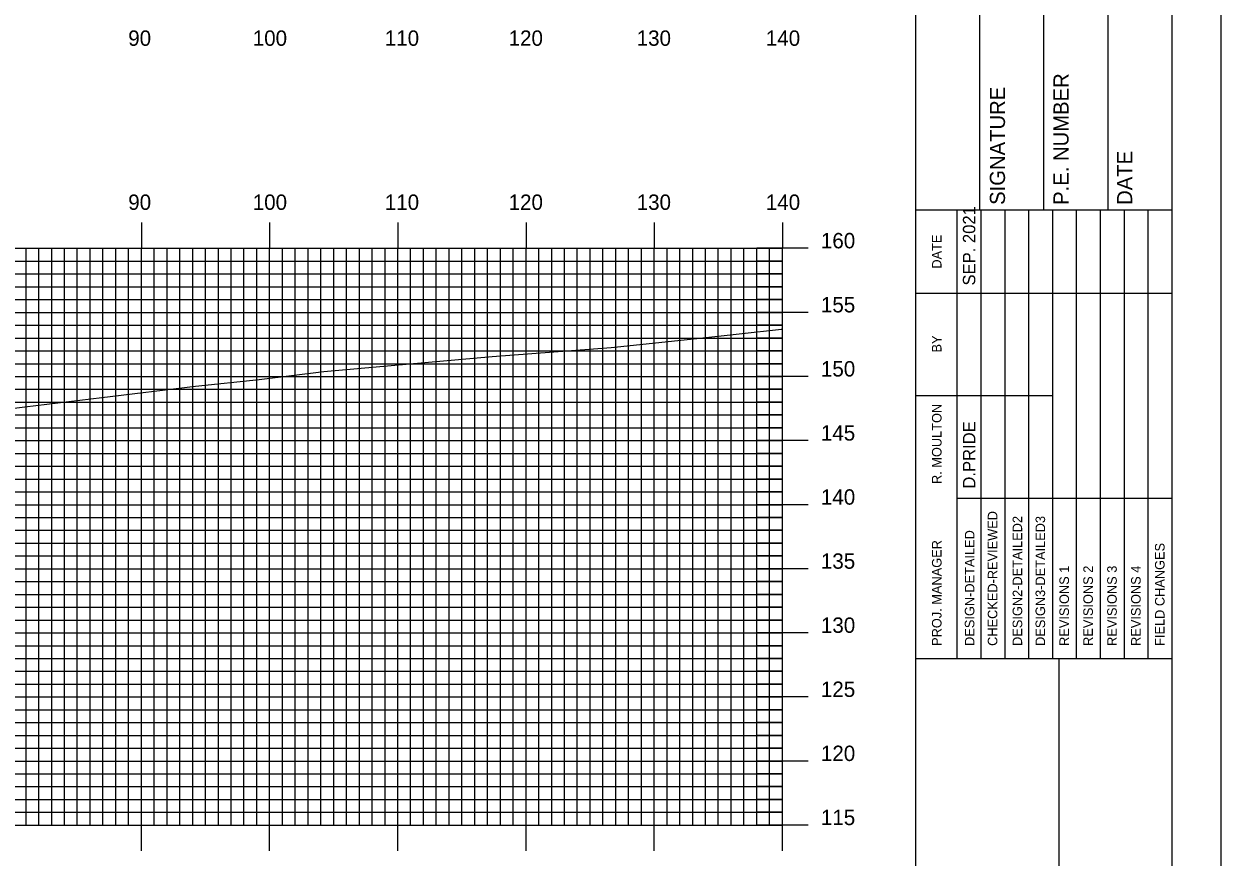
# Model space of a CAD drawing. Extents: x 1782647 to 1782990, y 442591 to 442811.
# Drawn here: x 1782893.8 to 1782987.2, y 442671.2 to 442736.2 of the extents above; entities that cross this region are included whole.
import ezdxf

# ---------------------------------------------------------------- set-up
doc = ezdxf.new("R2010")
doc.units = 0
for name, color, linetype in [('BORDER', 7, 'Continuous'), ('H_V ANNOTATION', 7, 'Continuous'), ('MAJOR', 7, 'Continuous'), ('MINOR', 7, 'Continuous'), ('PLOT BOUNDARY', 7, 'Continuous'), ('S_Roadway_Centerline', 7, 'Continuous')]:
    doc.layers.add(name, color=color, linetype=linetype)

msp = doc.modelspace()

# ---------------------------------------------------------------- linework, layer by layer
at = {"layer": 'BORDER'}
for p, q in [((1782963.347, 442596.665), (1782963.347, 442806.665)), ((1782968.347, 442721.671), (1782968.347, 442738.966)), ((1782968.347, 442721.671), (1782968.347, 442738.966)), ((1782973.347, 442721.671), (1782973.347, 442738.966)), ((1782973.347, 442721.671), (1782973.347, 442738.966)), ((1782978.347, 442721.671), (1782978.347, 442738.966)), ((1782978.347, 442721.671), (1782978.347, 442738.966)), ((1782963.347, 442721.671), (1782983.347, 442721.671)), ((1782963.347, 442721.671), (1782983.347, 442721.671)), ((1782963.347, 442686.671), (1782983.347, 442686.671)), ((1782963.347, 442686.671), (1782983.347, 442686.671)), ((1782974.529, 442616.671), (1782974.529, 442686.671)), ((1782974.529, 442616.671), (1782974.529, 442686.671))]:
    msp.add_line(p, q, dxfattribs=at)
msp.add_lwpolyline([(1782663.347, 442596.665), (1782983.347, 442596.665), (1782983.347, 442806.665), (1782663.347, 442806.665)], close=True, dxfattribs=at)
for points in [[(1782966.577, 442715.171), (1782966.577, 442721.671)], [(1782966.577, 442715.171), (1782966.577, 442721.671)], [(1782968.442, 442686.677), (1782968.442, 442721.671)], [(1782968.442, 442686.677), (1782968.442, 442721.671)], [(1782970.305, 442721.671), (1782970.305, 442686.677)], [(1782970.305, 442721.671), (1782970.305, 442686.677)], [(1782972.169, 442686.677), (1782972.169, 442721.671)], [(1782972.169, 442686.677), (1782972.169, 442721.671)], [(1782974.032, 442686.677), (1782974.032, 442721.671)], [(1782974.032, 442686.677), (1782974.032, 442721.671)], [(1782975.895, 442686.677), (1782975.895, 442721.671)], [(1782975.895, 442686.677), (1782975.895, 442721.671)], [(1782977.759, 442686.677), (1782977.759, 442721.671)], [(1782977.759, 442686.677), (1782977.759, 442721.671)], [(1782979.622, 442686.677), (1782979.622, 442721.671)], [(1782979.622, 442686.677), (1782979.622, 442721.671)], [(1782981.485, 442686.677), (1782981.485, 442721.671)], [(1782981.485, 442686.677), (1782981.485, 442721.671)], [(1782966.579, 442686.677), (1782966.579, 442720.259)], [(1782966.579, 442686.677), (1782966.579, 442720.259)], [(1782963.347, 442715.171), (1782983.347, 442715.171)], [(1782963.347, 442715.171), (1782983.347, 442715.171)], [(1782963.347, 442707.171), (1782966.579, 442707.171)], [(1782963.347, 442707.171), (1782966.579, 442707.171)], [(1782966.577, 442707.171), (1782974.03, 442707.171)], [(1782966.577, 442707.171), (1782974.03, 442707.171)], [(1782966.577, 442699.171), (1782983.347, 442699.171)], [(1782966.577, 442699.171), (1782983.347, 442699.171)]]:
    msp.add_lwpolyline(points, dxfattribs=at)
at = {"layer": 'MAJOR'}
for p, q in [((1782902.947, 442720.669), (1782902.947, 442718.665)), ((1782912.947, 442720.669), (1782912.947, 442718.665)), ((1782922.947, 442720.669), (1782922.947, 442718.665)), ((1782932.947, 442720.669), (1782932.947, 442718.665)), ((1782942.947, 442720.669), (1782942.947, 442718.665)), ((1782952.947, 442720.669), (1782952.947, 442718.665)), ((1782672.947, 442718.665), (1782952.947, 442718.665)), ((1782672.947, 442718.665), (1782952.947, 442718.665)), ((1782902.947, 442673.665), (1782902.947, 442718.665)), ((1782912.947, 442673.665), (1782912.947, 442718.665)), ((1782922.947, 442673.665), (1782922.947, 442718.665)), ((1782932.947, 442673.665), (1782932.947, 442718.665)), ((1782942.947, 442673.665), (1782942.947, 442718.665)), ((1782954.951, 442718.665), (1782950.943, 442718.665)), ((1782952.947, 442673.665), (1782952.947, 442718.665)), ((1782952.947, 442673.665), (1782952.947, 442718.665)), ((1782672.947, 442713.665), (1782952.947, 442713.665)), ((1782954.951, 442713.665), (1782950.943, 442713.665)), ((1782672.947, 442708.665), (1782952.947, 442708.665)), ((1782954.951, 442708.665), (1782950.943, 442708.665)), ((1782672.947, 442703.665), (1782952.947, 442703.665)), ((1782954.951, 442703.665), (1782950.943, 442703.665)), ((1782672.947, 442698.665), (1782952.947, 442698.665)), ((1782954.951, 442698.665), (1782950.943, 442698.665)), ((1782672.947, 442693.665), (1782952.947, 442693.665)), ((1782954.951, 442693.665), (1782950.943, 442693.665)), ((1782672.947, 442688.665), (1782952.947, 442688.665)), ((1782954.951, 442688.665), (1782950.943, 442688.665)), ((1782672.947, 442683.665), (1782952.947, 442683.665)), ((1782954.951, 442683.665), (1782950.943, 442683.665)), ((1782672.947, 442678.665), (1782952.947, 442678.665)), ((1782954.951, 442678.665), (1782950.943, 442678.665)), ((1782672.947, 442673.665), (1782952.947, 442673.665)), ((1782672.947, 442673.665), (1782952.947, 442673.665)), ((1782902.947, 442671.661), (1782902.947, 442673.665)), ((1782912.947, 442671.661), (1782912.947, 442673.665)), ((1782922.947, 442671.661), (1782922.947, 442673.665)), ((1782932.947, 442671.661), (1782932.947, 442673.665)), ((1782942.947, 442671.661), (1782942.947, 442673.665)), ((1782954.951, 442673.665), (1782950.943, 442673.665)), ((1782952.947, 442671.661), (1782952.947, 442673.665))]:
    msp.add_line(p, q, dxfattribs=at)
at = {"layer": 'MINOR'}
for p, q in [((1782893.947, 442673.665), (1782893.947, 442718.665)), ((1782894.947, 442673.665), (1782894.947, 442718.665)), ((1782895.947, 442673.665), (1782895.947, 442718.665)), ((1782896.947, 442673.665), (1782896.947, 442718.665)), ((1782897.947, 442673.665), (1782897.947, 442718.665)), ((1782898.947, 442673.665), (1782898.947, 442718.665)), ((1782899.947, 442673.665), (1782899.947, 442718.665)), ((1782900.947, 442673.665), (1782900.947, 442718.665)), ((1782901.947, 442673.665), (1782901.947, 442718.665)), ((1782903.947, 442673.665), (1782903.947, 442718.665)), ((1782904.947, 442673.665), (1782904.947, 442718.665)), ((1782905.947, 442673.665), (1782905.947, 442718.665)), ((1782906.947, 442673.665), (1782906.947, 442718.665)), ((1782907.947, 442673.665), (1782907.947, 442718.665)), ((1782908.947, 442673.665), (1782908.947, 442718.665)), ((1782909.947, 442673.665), (1782909.947, 442718.665)), ((1782910.947, 442673.665), (1782910.947, 442718.665)), ((1782911.947, 442673.665), (1782911.947, 442718.665)), ((1782913.947, 442673.665), (1782913.947, 442718.665)), ((1782914.947, 442673.665), (1782914.947, 442718.665)), ((1782915.947, 442673.665), (1782915.947, 442718.665)), ((1782916.947, 442673.665), (1782916.947, 442718.665)), ((1782917.947, 442673.665), (1782917.947, 442718.665)), ((1782918.947, 442673.665), (1782918.947, 442718.665)), ((1782919.947, 442673.665), (1782919.947, 442718.665)), ((1782920.947, 442673.665), (1782920.947, 442718.665)), ((1782921.947, 442673.665), (1782921.947, 442718.665)), ((1782923.947, 442673.665), (1782923.947, 442718.665)), ((1782924.947, 442673.665), (1782924.947, 442718.665)), ((1782925.947, 442673.665), (1782925.947, 442718.665)), ((1782926.947, 442673.665), (1782926.947, 442718.665)), ((1782927.947, 442673.665), (1782927.947, 442718.665)), ((1782928.947, 442673.665), (1782928.947, 442718.665)), ((1782929.947, 442673.665), (1782929.947, 442718.665)), ((1782930.947, 442673.665), (1782930.947, 442718.665)), ((1782931.947, 442673.665), (1782931.947, 442718.665)), ((1782933.947, 442673.665), (1782933.947, 442718.665)), ((1782934.947, 442673.665), (1782934.947, 442718.665)), ((1782935.947, 442673.665), (1782935.947, 442718.665)), ((1782936.947, 442673.665), (1782936.947, 442718.665)), ((1782937.947, 442673.665), (1782937.947, 442718.665)), ((1782938.947, 442673.665), (1782938.947, 442718.665)), ((1782939.947, 442673.665), (1782939.947, 442718.665)), ((1782940.947, 442673.665), (1782940.947, 442718.665)), ((1782941.947, 442673.665), (1782941.947, 442718.665)), ((1782943.947, 442673.665), (1782943.947, 442718.665)), ((1782944.947, 442673.665), (1782944.947, 442718.665)), ((1782945.947, 442673.665), (1782945.947, 442718.665)), ((1782946.947, 442673.665), (1782946.947, 442718.665)), ((1782947.947, 442673.665), (1782947.947, 442718.665)), ((1782948.947, 442673.665), (1782948.947, 442718.665)), ((1782949.947, 442673.665), (1782949.947, 442718.665)), ((1782950.947, 442673.665), (1782950.947, 442718.665)), ((1782951.947, 442673.665), (1782951.947, 442718.665)), ((1782672.947, 442717.665), (1782952.947, 442717.665)), ((1782952.947, 442717.665), (1782950.943, 442717.665)), ((1782672.947, 442716.665), (1782952.947, 442716.665)), ((1782952.947, 442716.665), (1782950.943, 442716.665)), ((1782672.947, 442715.665), (1782952.947, 442715.665)), ((1782952.947, 442715.665), (1782950.943, 442715.665)), ((1782672.947, 442714.665), (1782952.947, 442714.665)), ((1782952.947, 442714.665), (1782950.943, 442714.665)), ((1782672.947, 442712.665), (1782952.947, 442712.665)), ((1782952.947, 442712.665), (1782950.943, 442712.665)), ((1782672.947, 442711.665), (1782952.947, 442711.665)), ((1782952.947, 442711.665), (1782950.943, 442711.665)), ((1782672.947, 442710.665), (1782952.947, 442710.665)), ((1782952.947, 442710.665), (1782950.943, 442710.665)), ((1782672.947, 442709.665), (1782952.947, 442709.665)), ((1782952.947, 442709.665), (1782950.943, 442709.665)), ((1782672.947, 442707.665), (1782952.947, 442707.665)), ((1782952.947, 442707.665), (1782950.943, 442707.665)), ((1782672.947, 442706.665), (1782952.947, 442706.665)), ((1782952.947, 442706.665), (1782950.943, 442706.665)), ((1782672.947, 442705.665), (1782952.947, 442705.665)), ((1782952.947, 442705.665), (1782950.943, 442705.665)), ((1782672.947, 442704.665), (1782952.947, 442704.665)), ((1782952.947, 442704.665), (1782950.943, 442704.665)), ((1782672.947, 442702.665), (1782952.947, 442702.665)), ((1782952.947, 442702.665), (1782950.943, 442702.665)), ((1782672.947, 442701.665), (1782952.947, 442701.665)), ((1782952.947, 442701.665), (1782950.943, 442701.665)), ((1782672.947, 442700.665), (1782952.947, 442700.665)), ((1782952.947, 442700.665), (1782950.943, 442700.665)), ((1782672.947, 442699.665), (1782952.947, 442699.665)), ((1782952.947, 442699.665), (1782950.943, 442699.665)), ((1782672.947, 442697.665), (1782952.947, 442697.665)), ((1782952.947, 442697.665), (1782950.943, 442697.665)), ((1782672.947, 442696.665), (1782952.947, 442696.665)), ((1782952.947, 442696.665), (1782950.943, 442696.665)), ((1782672.947, 442695.665), (1782952.947, 442695.665)), ((1782952.947, 442695.665), (1782950.943, 442695.665)), ((1782672.947, 442694.665), (1782952.947, 442694.665)), ((1782952.947, 442694.665), (1782950.943, 442694.665)), ((1782672.947, 442692.665), (1782952.947, 442692.665)), ((1782952.947, 442692.665), (1782950.943, 442692.665)), ((1782672.947, 442691.665), (1782952.947, 442691.665)), ((1782952.947, 442691.665), (1782950.943, 442691.665)), ((1782672.947, 442690.665), (1782952.947, 442690.665)), ((1782952.947, 442690.665), (1782950.943, 442690.665)), ((1782672.947, 442689.665), (1782952.947, 442689.665)), ((1782952.947, 442689.665), (1782950.943, 442689.665)), ((1782672.947, 442687.665), (1782952.947, 442687.665)), ((1782952.947, 442687.665), (1782950.943, 442687.665)), ((1782672.947, 442686.665), (1782952.947, 442686.665)), ((1782952.947, 442686.665), (1782950.943, 442686.665)), ((1782672.947, 442685.665), (1782952.947, 442685.665)), ((1782952.947, 442685.665), (1782950.943, 442685.665)), ((1782672.947, 442684.665), (1782952.947, 442684.665)), ((1782952.947, 442684.665), (1782950.943, 442684.665)), ((1782672.947, 442682.665), (1782952.947, 442682.665)), ((1782952.947, 442682.665), (1782950.943, 442682.665)), ((1782672.947, 442681.665), (1782952.947, 442681.665)), ((1782952.947, 442681.665), (1782950.943, 442681.665)), ((1782672.947, 442680.665), (1782952.947, 442680.665)), ((1782952.947, 442680.665), (1782950.943, 442680.665)), ((1782672.947, 442679.665), (1782952.947, 442679.665)), ((1782952.947, 442679.665), (1782950.943, 442679.665)), ((1782672.947, 442677.665), (1782952.947, 442677.665)), ((1782952.947, 442677.665), (1782950.943, 442677.665)), ((1782672.947, 442676.665), (1782952.947, 442676.665)), ((1782952.947, 442676.665), (1782950.943, 442676.665)), ((1782672.947, 442675.665), (1782952.947, 442675.665)), ((1782952.947, 442675.665), (1782950.943, 442675.665)), ((1782672.947, 442674.665), (1782952.947, 442674.665)), ((1782952.947, 442674.665), (1782950.943, 442674.665))]:
    msp.add_line(p, q, dxfattribs=at)
at = {"layer": 'PLOT BOUNDARY'}
msp.add_lwpolyline([(1782647.16, 442590.547), (1782987.16, 442590.547), (1782987.16, 442810.547), (1782647.16, 442810.547)], close=True, dxfattribs=at)
at = {"layer": 'S_Roadway_Centerline'}
msp.add_lwpolyline([(1782884.098, 442705.086), (1782893.859, 442706.3), (1782899.862, 442707.022), (1782907.169, 442707.922), (1782912.136, 442708.432), (1782917.175, 442709.049), (1782930.318, 442710.225), (1782939.582, 442710.921), (1782946.281, 442711.618), (1782952.883, 442712.367), (1782952.947, 442712.372)], dxfattribs=at)

# ---------------------------------------------------------------- texts
at = {"layer": 'BORDER'}
for s, height, p in [('P.E. NUMBER', 1.1811, (1782975.269, 442722.055)), ('P.E. NUMBER', 1.1811, (1782975.269, 442722.055)), ('SIGNATURE', 1.1811, (1782970.308, 442722.055)), ('SIGNATURE', 1.1811, (1782970.308, 442722.055)), ('DATE', 1.1811, (1782980.229, 442722.055)), ('DATE', 1.1811, (1782980.229, 442722.055)), ('SEP. 2021', 0.9691, (1782967.993, 442715.762)), ('DATE', 0.7428, (1782965.356, 442717.083)), ('DATE', 0.7428, (1782965.356, 442717.083)), ('BY', 0.7428, (1782965.356, 442710.541)), ('BY', 0.7428, (1782965.356, 442710.541)), ('R. MOULTON', 0.7455, (1782965.356, 442700.276)), ('D.PRIDE', 0.9691, (1782967.993, 442699.917)), ('CHECKED-REVIEWED', 0.7455, (1782969.709, 442687.647)), ('CHECKED-REVIEWED', 0.7455, (1782969.709, 442687.647)), ('DESIGN2-DETAILED2', 0.7455, (1782971.647, 442687.647)), ('DESIGN2-DETAILED2', 0.7455, (1782971.647, 442687.647)), ('DESIGN3-DETAILED3', 0.7455, (1782973.436, 442687.647)), ('DESIGN3-DETAILED3', 0.7455, (1782973.436, 442687.647)), ('DESIGN-DETAILED', 0.7455, (1782967.92, 442687.647)), ('DESIGN-DETAILED', 0.7455, (1782967.92, 442687.647)), ('PROJ. MANAGER', 0.7455, (1782965.356, 442687.647)), ('PROJ. MANAGER', 0.7455, (1782965.356, 442687.647)), ('FIELD CHANGES', 0.7455, (1782982.753, 442687.647)), ('FIELD CHANGES', 0.7455, (1782982.753, 442687.647)), ('REVISIONS 1', 0.7455, (1782975.299, 442687.647)), ('REVISIONS 1', 0.7455, (1782975.299, 442687.647)), ('REVISIONS 2', 0.7455, (1782977.162, 442687.647)), ('REVISIONS 2', 0.7455, (1782977.162, 442687.647)), ('REVISIONS 3', 0.7455, (1782979.026, 442687.647)), ('REVISIONS 3', 0.7455, (1782979.026, 442687.647)), ('REVISIONS 4', 0.7455, (1782980.889, 442687.647)), ('REVISIONS 4', 0.7455, (1782980.889, 442687.647))]:
    msp.add_text(s, height=height, rotation=90, dxfattribs=at).set_placement(p)
at = {"layer": 'H_V ANNOTATION'}
for s, p in [('90', (1782901.919, 442734.465)), ('100', (1782911.63, 442734.465)), ('110', (1782921.93, 442734.465)), ('120', (1782931.588, 442734.465)), ('130', (1782941.577, 442734.465)), ('140', (1782951.652, 442734.465)), ('90', (1782901.919, 442721.665)), ('100', (1782911.63, 442721.665)), ('110', (1782921.93, 442721.665)), ('120', (1782931.588, 442721.665)), ('130', (1782941.577, 442721.665)), ('140', (1782951.652, 442721.665)), ('160', (1782955.947, 442718.665)), ('155', (1782955.947, 442713.665)), ('150', (1782955.947, 442708.665)), ('145', (1782955.947, 442703.665)), ('140', (1782955.947, 442698.665)), ('135', (1782955.947, 442693.665)), ('130', (1782955.947, 442688.665)), ('125', (1782955.947, 442683.665)), ('120', (1782955.947, 442678.665)), ('115', (1782955.947, 442673.665))]:
    msp.add_text(s, height=1.2, dxfattribs=at).set_placement(p)

doc.saveas('drawing.dxf')
